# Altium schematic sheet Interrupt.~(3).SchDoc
size A; SheetNumber: 1; SheetTotal: 1
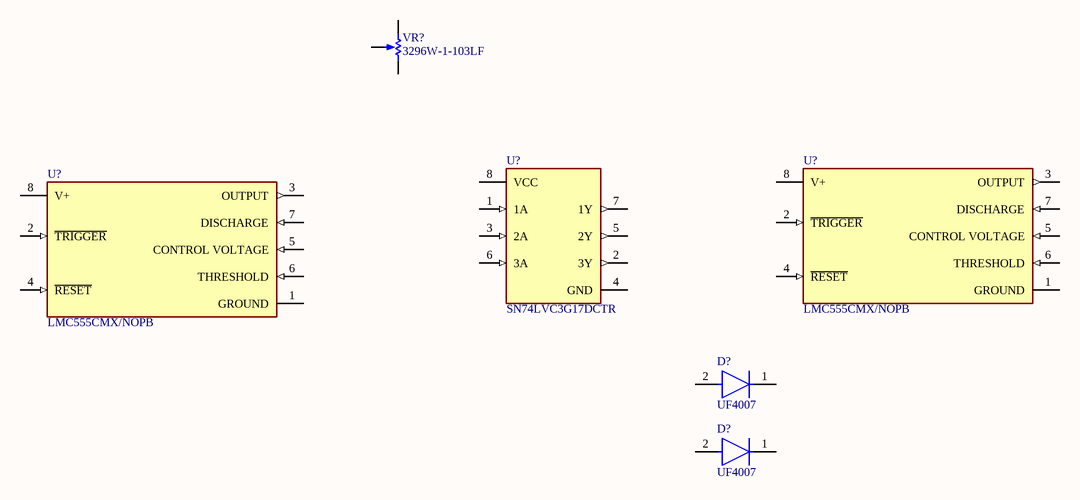
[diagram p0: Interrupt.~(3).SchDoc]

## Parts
(Parts that share a designator on the sheet are numbered #1, #2 ... from top to bottom, then left to right.)
D?#1  UF4007  [FP-017AH-MFG]
D?#2  UF4007  [FP-017AH-MFG]
U?#1  SN74LVC3G17DCTR  [FP-DCT0008A-MFG]
U?#2  LMC555CMX/NOPB  [FP-D0008A-MFG]
U?#3  LMC555CMX/NOPB  [FP-D0008A-MFG]
VR?  3296W-1-103LF  [BOUR-3296W]

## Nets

Not connected (* = marked no-connect by the designer): D?#1 1(C) 2(A); D?#2 1(C) 2(A); U?#1 1(1A) 2(3Y) 3(2A) 4(GND) 5(2Y) 6(3A) 7(1Y) 8(VCC); U?#2 1(GROUND) 2(~{TRIGGER}) 3(OUTPUT) 4(~{RESET}) 5(CONTROL_VOLTAGE) 6(THRESHOLD) 7(DISCHARGE) 8(V+); U?#3 1(GROUND) 2(~{TRIGGER}) 3(OUTPUT) 4(~{RESET}) 5(CONTROL_VOLTAGE) 6(THRESHOLD) 7(DISCHARGE) 8(V+); VR? 1(CCW) 2(S) 3(CW)

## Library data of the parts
D?#1 D?#2 = CMP-2000-05028-2: DIODE GEN PURP 1KV 1A DO41; Manufacturer: ON Semiconductor; Capacitance: 17pF; Max Surge Forward Current: 30A; Description: Diode Standard 1000V 1A Through Hole DO-204AL (DO-41); Max Repetitive Reverse Voltage: 1000V; Value: 17pF; Max Junction Temp: +150°C; Peak Reverse Current: 10uA
U?#1 = CMP-0859-00525-5: IC BUFFER NON-INVERT 5.5V SM8; Manufacturer: Texas Instruments; Logic Function Desc: Non-Inverting; Propagation Delay: 5.1ns; Number Of Inputs: 3; Description: Buffer, Non-Inverting 3 Element 1 Bit per Element Push-Pull Output SM8 (SSOP); Standoff Height: 0mm; Nominal Supply Current: 10uA; Min Supply Voltage: 1.65V
U?#2 U?#3 = CMP-04858-000001-1: IC OSC SINGLE TIMER 3MHZ 8-SOIC; Manufacturer: Texas Instruments; Description: 555 Type, Timer/Oscillator (Single) IC 3MHz 8-SOIC; Number Of Timers/Counters: 1; Max Supply Voltage: 15V; Standoff Height: 0.11mm; Propagation Delay: 100ns; Nominal Supply Current: 50-150uA; Min Supply Voltage: 1.5V
VR? = CMP-1747-00001-1: Square Trimpot(R) Trimming Potentiometer, 10 KOhm, +/- 10%, 0.5 W, -55 to 125 degC, 3-Pin THD, RoHS, Tube; Voltage Rating: 75 V; Resistance: 120 Ohm; Tolerance: 1%; Power Rating: 100 mW; Case\Package: 0603; Type (Resistor): Thick Film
